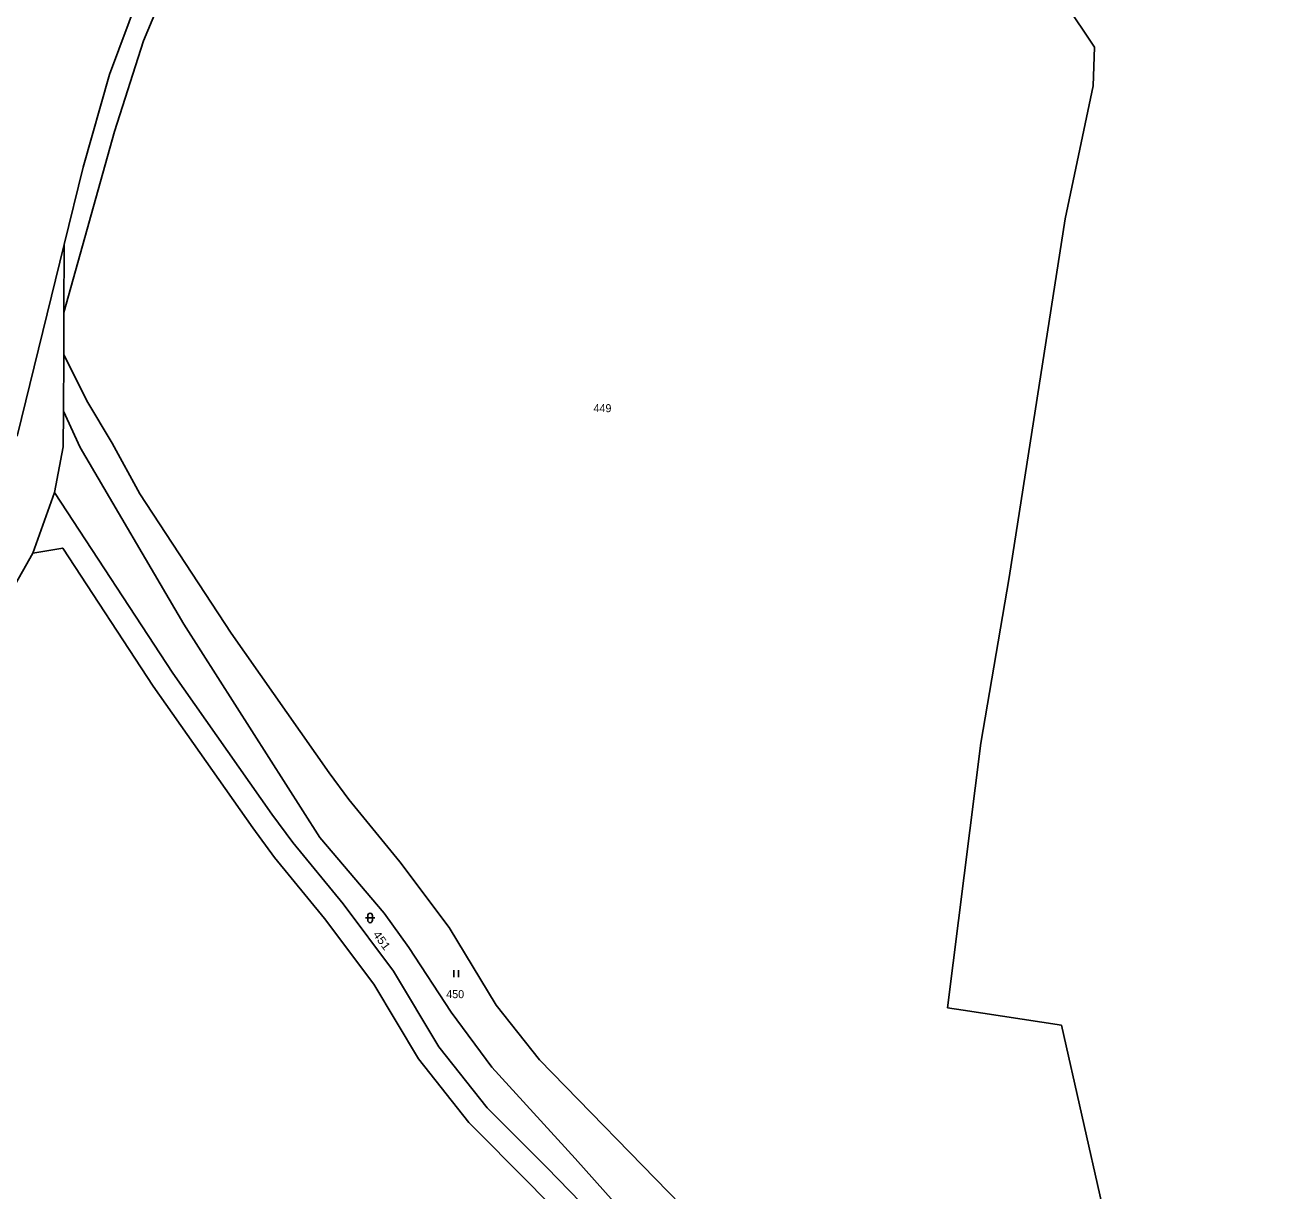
# Model space of a CAD drawing. Extents: x -769392 to -767038, y -1018329 to -1015269.
# Drawn here: x -768034.4 to -767768.8, y -1015766.2 to -1015518.7 of the extents above; entities that cross this region are included whole.
import ezdxf

# ---------------------------------------------------------------- set-up
doc = ezdxf.new("R2010")
doc.units = 0
doc.header["$LTSCALE"] = 0.68
doc.layers.add('1', color=7, linetype='Continuous', lineweight=25)
doc.layers.add('3', color=7, linetype='Continuous', lineweight=25)
doc.layers.add('2', color=7, linetype='Continuous')

msp = doc.modelspace()

# ---------------------------------------------------------------- linework, layer by layer
at = {"layer": '1'}
for p, q in [((-768009.31, -1015509.93), (-768016.5, -1015529.16)), ((-767813.62, -1015513.94), (-767807.32, -1015523.38)), ((-767807.32, -1015523.38), (-767807.62, -1015531.58)), ((-768016.5, -1015529.16), (-768022.06, -1015548.83)), ((-767807.62, -1015531.58), (-767813.57, -1015559.79)), ((-768022.06, -1015548.83), (-768026.1, -1015565.25)), ((-767813.57, -1015559.79), (-767825.42, -1015635.96)), ((-768026.1, -1015565.25), (-768036.1, -1015605.96)), ((-768026.18, -1015579.73), (-768026.1, -1015565.25)), ((-768026.23, -1015588.62), (-768026.18, -1015579.73)), ((-768026.29, -1015600.63), (-768026.23, -1015588.62)), ((-768032.78, -1015630.79), (-768028.19, -1015617.91)), ((-767825.42, -1015635.96), (-767831.5, -1015671.13)), ((-767831.5, -1015671.13), (-767838.54, -1015727.31)), ((-767838.54, -1015727.31), (-767835.2, -1015727.82)), ((-767835.2, -1015727.82), (-767814.33, -1015731.02)), ((-767814.33, -1015731.02), (-767805.7, -1015769.26))]:
    msp.add_line(p, q, dxfattribs=at)
for points in [[(-768026.18, -1015579.73), (-768015.46, -1015541.3), (-768009.26, -1015521.99), (-767996.16, -1015490.74), (-767984.44, -1015470.06), (-767970.88, -1015449.61), (-767961.24, -1015438.53)], [(-768026.23, -1015588.62), (-768021.28, -1015598.42), (-768015.93, -1015607.43), (-768010.09, -1015618.18), (-767990.66, -1015647.78), (-767969.86, -1015677.42), (-767965.65, -1015683.12), (-767954.84, -1015696.33), (-767944.36, -1015710.3), (-767934.37, -1015726.79), (-767925.2, -1015738.37), (-767895.08, -1015769.25), (-767883.4, -1015783.54), (-767870.5, -1015801.03), (-767863.61, -1015809.82), (-767851.68, -1015827.46), (-767849.73, -1015830.74)], [(-768028.19, -1015617.91), (-768026.32, -1015608.24), (-768026.29, -1015600.63)], [(-767859.4, -1015836.62), (-767872.54, -1015815.98), (-767880.29, -1015804.69), (-767889.07, -1015792.58), (-767901.17, -1015777.71), (-767917.59, -1015759.29), (-767935.31, -1015739.91), (-767943.91, -1015728.27), (-767952.95, -1015714.52), (-767958.16, -1015707.22), (-767971.8, -1015691.16), (-768000.68, -1015645.86), (-768022.75, -1015608.36), (-768026.29, -1015600.63)], [(-767862.53, -1015838.53), (-767864.6, -1015835.09), (-767875.3, -1015819.22), (-767882.4, -1015810.17), (-767895.55, -1015792.34), (-767906.81, -1015778.6), (-767923.66, -1015761.23), (-767936.28, -1015748.55), (-767946.57, -1015735.61), (-767956.21, -1015719.51), (-767966.91, -1015705.24), (-767977.57, -1015692.24), (-767982, -1015686.24), (-768003.03, -1015656.27), (-768028.19, -1015617.91)], [(-768032.78, -1015630.79), (-768026.42, -1015629.72), (-768007.22, -1015659.01), (-767986.09, -1015689.11), (-767981.44, -1015695.41), (-767970.85, -1015708.33), (-767960.37, -1015722.3), (-767950.86, -1015738.18), (-767940.19, -1015751.66), (-767927.2, -1015764.76), (-767910.54, -1015781.93), (-767899.5, -1015795.41), (-767886.42, -1015813.14), (-767879.35, -1015822.16), (-767868.82, -1015837.78), (-767859.46, -1015853.31), (-767839.83, -1015886.35), (-767827.67, -1015907.62), (-767817.21, -1015924.68), (-767803.52, -1015945.16), (-767789.08, -1015963.94), (-767776.19, -1015979.12), (-767768.79, -1015986.33)], [(-768102.72, -1015799.16), (-768102.1, -1015790.03), (-768098.18, -1015776.92), (-768095.07, -1015769.01), (-768068.74, -1015715.9), (-768057.97, -1015694.98), (-768044.47, -1015662.72), (-768037.18, -1015638.56), (-768032.78, -1015630.79)]]:
    msp.add_lwpolyline(points, dxfattribs=at)
at = {"layer": '3'}
for p, q in [((-767962.161, -1015708.251), (-767960.159, -1015708.251)), ((-767961.661, -1015707.751), (-767961.661, -1015708.752)), ((-767960.659, -1015708.752), (-767960.659, -1015707.751)), ((-767943.371, -1015720.82), (-767943.371, -1015719.32)), ((-767942.37, -1015720.82), (-767942.37, -1015719.32))]:
    msp.add_line(p, q, dxfattribs=at)
for centre, start, end in [((-767961.16, -1015707.7509), 0, 180), ((-767961.16, -1015708.7509), 180, 359.98789)]:
    msp.add_arc(centre, 0.5, start, end, dxfattribs=at)

# ---------------------------------------------------------------- texts
at = {"layer": '2'}
for s, p in [('449', (-767913.71, -1015600.855)), ('450', (-767944.99, -1015725.275))]:
    msp.add_text(s, height=1.7, dxfattribs=at).set_placement(p)
at = {"layer": '2', "width": 1.15}
msp.add_text('451', height=1.7, rotation=306, dxfattribs=at).set_placement((-767960.643, -1015711.759))

doc.saveas('drawing.dxf')
